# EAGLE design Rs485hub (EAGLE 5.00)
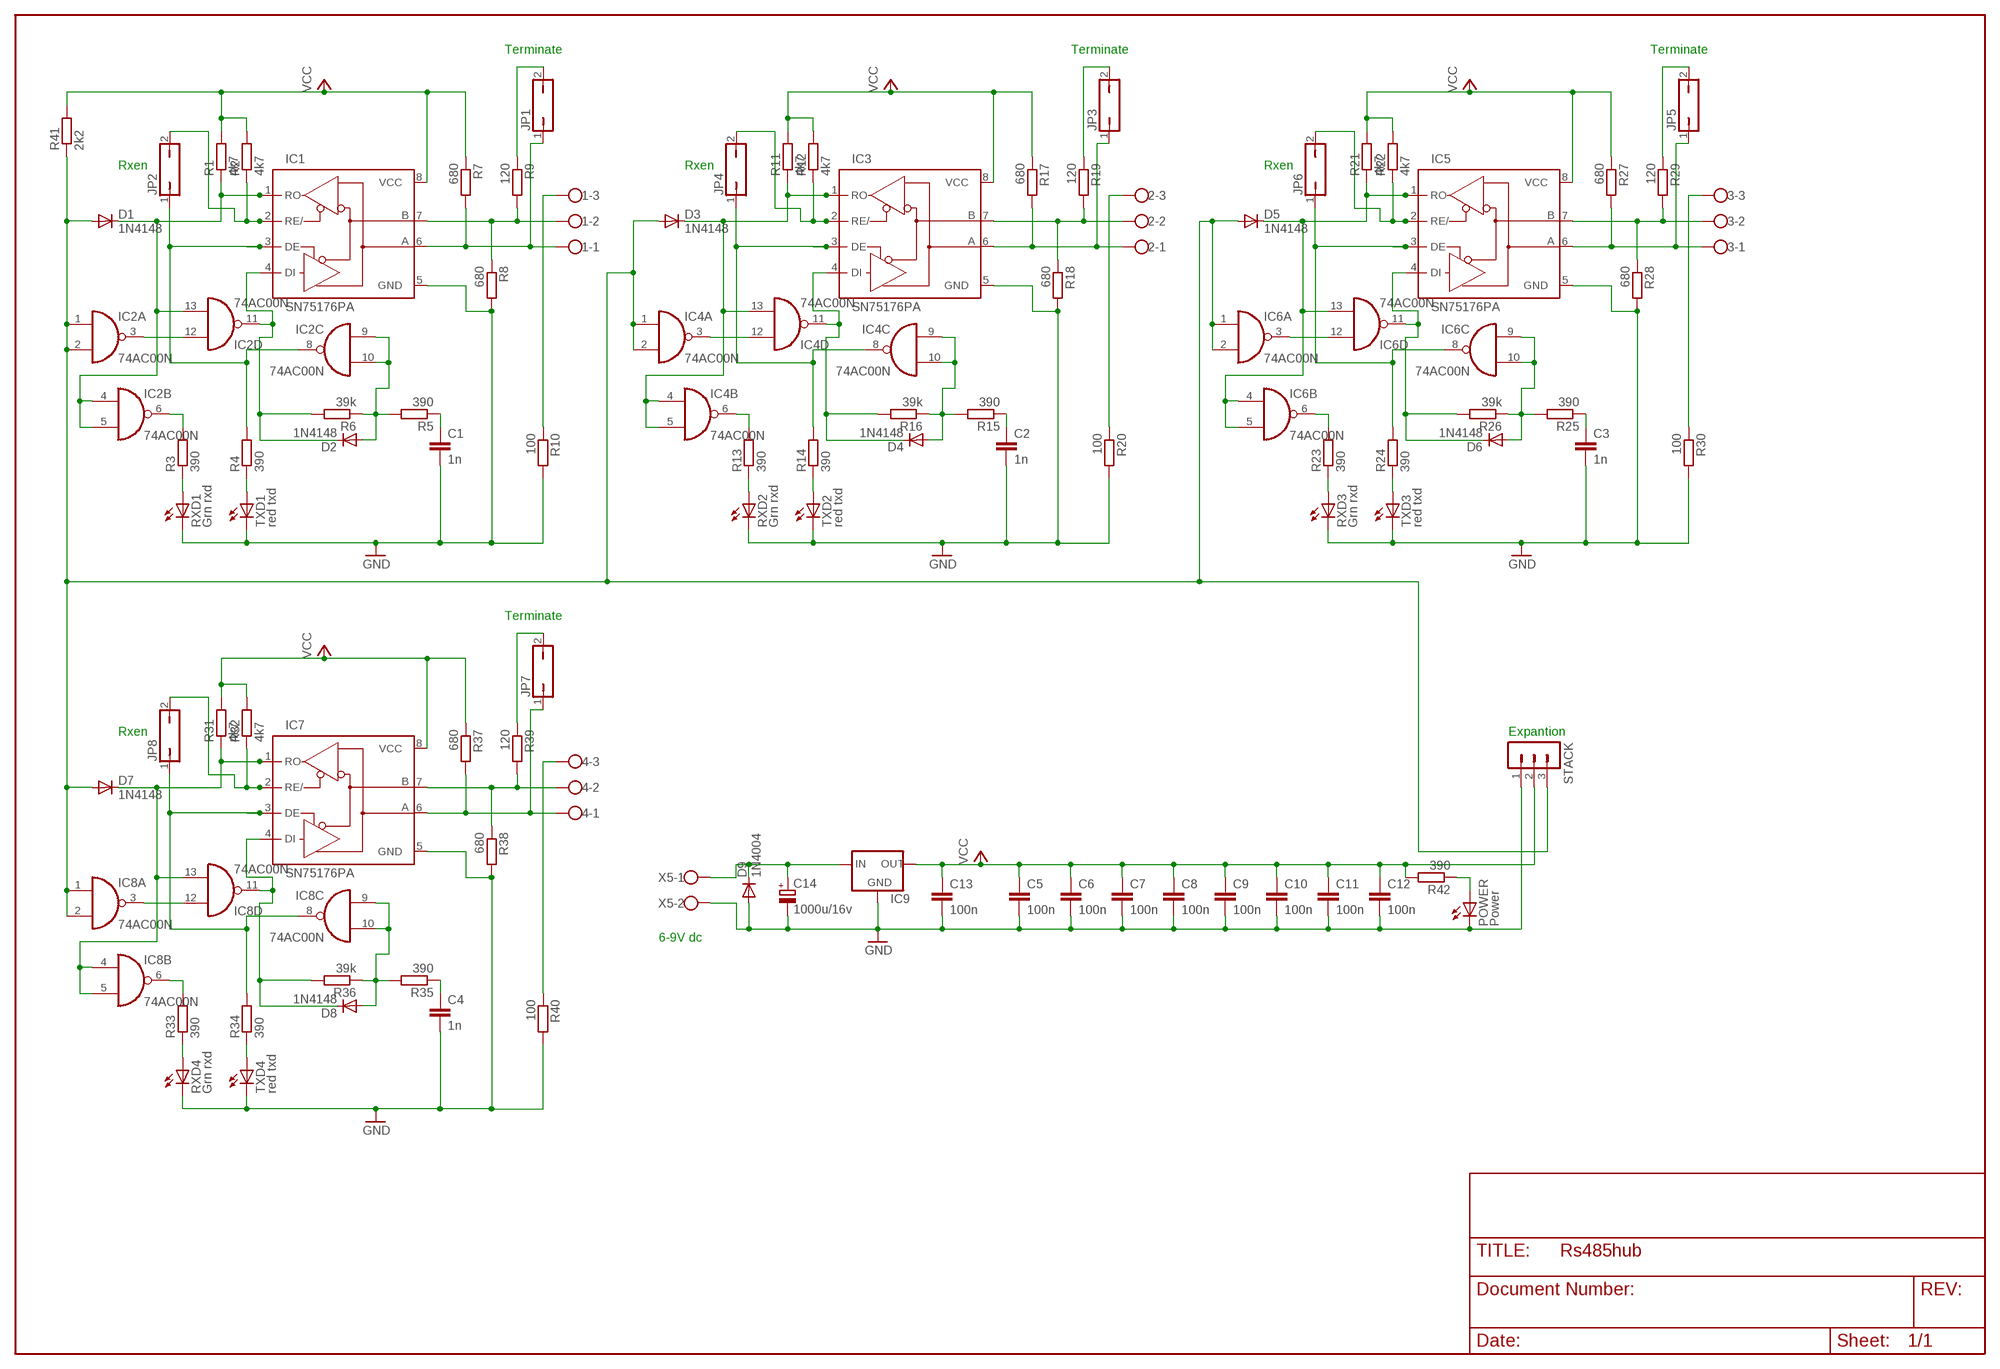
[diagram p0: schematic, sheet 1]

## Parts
1  W237-103  [W237-103]
2  W237-103  [W237-103]
3  W237-103  [W237-103]
4  W237-103  [W237-103]
C1  1n  C2,5-3  [C2.5-3]
C2  1n  C2,5-3  [C2.5-3]
C3  1n  C2,5-3  [C2.5-3]
C4  1n  C2,5-3  [C2.5-3]
C5  100n  C2,5-3  [C2.5-3]
C6  100n  C2,5-3  [C2.5-3]
C7  100n  C2,5-3  [C2.5-3]
C8  100n  C2,5-3  [C2.5-3]
C9  100n  C2,5-3  [C2.5-3]
C10  100n  C2,5-3  [C2.5-3]
C11  100n  C2,5-3  [C2.5-3]
C12  100n  C2,5-3  [C2.5-3]
C13  100n  C2,5-3  [C2.5-3]
C14  1000u/16v  CPOL-EUE5-13  [E5-13]
D1  1N4148  [DO35-10]
D2  1N4148  [DO35-10]
D3  1N4148  [DO35-10]
D4  1N4148  [DO35-10]
D5  1N4148  [DO35-10]
D6  1N4148  [DO35-10]
D7  1N4148  [DO35-10]
D8  1N4148  [DO35-10]
D9  1N4004  [DO41-10]
IC1  SN75176PA  [DIL08]
IC2  74AC00N  [DIL14]
IC3  SN75176PA  [DIL08]
IC4  74AC00N  [DIL14]
IC5  SN75176PA  [DIL08]
IC6  74AC00N  [DIL14]
IC7  SN75176PA  [DIL08]
IC8  74AC00N  [DIL14]
IC9  78XXS  [78XXS]
JP1  JP1Q  [JP1]
JP2  JP1Q  [JP1]
JP3  JP1Q  [JP1]
JP4  JP1Q  [JP1]
JP5  JP1Q  [JP1]
JP6  JP1Q  [JP1]
JP7  JP1Q  [JP1]
JP8  JP1Q  [JP1]
POWER  Power  LED3MM  [LED3MM]
R1  4k7  R-EU_0309/10  [0309/10]
R2  4k7  R-EU_0309/10  [0309/10]
R3  390  R-EU_0309/10  [0309/10]
R4  390  R-EU_0309/10  [0309/10]
R5  390  R-EU_0309/10  [0309/10]
R6  39k  R-EU_0309/10  [0309/10]
R7  680  R-EU_0309/10  [0309/10]
R8  680  R-EU_0309/10  [0309/10]
R9  120  R-EU_0309/10  [0309/10]
R10  100  R-EU_0309/10  [0309/10]
R11  4k7  R-EU_0309/10  [0309/10]
R12  4k7  R-EU_0309/10  [0309/10]
R13  390  R-EU_0309/10  [0309/10]
R14  390  R-EU_0309/10  [0309/10]
R15  390  R-EU_0309/10  [0309/10]
R16  39k  R-EU_0309/10  [0309/10]
R17  680  R-EU_0309/10  [0309/10]
R18  680  R-EU_0309/10  [0309/10]
R19  120  R-EU_0309/10  [0309/10]
R20  100  R-EU_0309/10  [0309/10]
R21  4k7  R-EU_0309/10  [0309/10]
R22  4k7  R-EU_0309/10  [0309/10]
R23  390  R-EU_0309/10  [0309/10]
R24  390  R-EU_0309/10  [0309/10]
R25  390  R-EU_0309/10  [0309/10]
R26  39k  R-EU_0309/10  [0309/10]
R27  680  R-EU_0309/10  [0309/10]
R28  680  R-EU_0309/10  [0309/10]
R29  120  R-EU_0309/10  [0309/10]
R30  100  R-EU_0309/10  [0309/10]
R31  4k7  R-EU_0309/10  [0309/10]
R32  4k7  R-EU_0309/10  [0309/10]
R33  390  R-EU_0309/10  [0309/10]
R34  390  R-EU_0309/10  [0309/10]
R35  390  R-EU_0309/10  [0309/10]
R36  39k  R-EU_0309/10  [0309/10]
R37  680  R-EU_0309/10  [0309/10]
R38  680  R-EU_0309/10  [0309/10]
R39  120  R-EU_0309/10  [0309/10]
R40  100  R-EU_0309/10  [0309/10]
R41  2k2  R-EU_0309/10  [0309/10]
R42  390  R-EU_0309/10  [0309/10]
RXD1  Grn rxd  LED3MM  [LED3MM]
RXD2  Grn rxd  LED3MM  [LED3MM]
RXD3  Grn rxd  LED3MM  [LED3MM]
RXD4  Grn rxd  LED3MM  [LED3MM]
STACK  MA03-1  [MA03-1]
TXD1  red txd  LED3MM  [LED3MM]
TXD2  red txd  LED3MM  [LED3MM]
TXD3  red txd  LED3MM  [LED3MM]
TXD4  red txd  LED3MM  [LED3MM]
X5  W237-102  [W237-102]

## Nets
DATABUS: D1.A D3.A D5.A D7.A IC2.1(A:I0) IC2.2(A:I1) IC4.1(A:I0) IC4.2(A:I1) IC6.1(A:I0) IC6.2(A:I1) IC8.1(A:I0) IC8.2(A:I1) R41.1 STACK.3
GND [Gnd]: C1.2 C2.2 C3.2 C4.2 C5.2 C6.2 C7.2 C8.2 C9.2 C10.2 C11.2 C12.2 C13.2 C14.- D9.A IC1.5(GND) IC3.5(GND) IC5.5(GND) IC7.5(GND) IC9.GND POWER.K(C) R8.2 R10.2 R18.2 R20.2 R28.2 R30.2 R38.2 R40.2 RXD1.K(C) RXD2.K(C) RXD3.K(C) RXD4.K(C) STACK.1 TXD1.K(C) TXD2.K(C) TXD3.K(C) TXD4.K(C) X5.2
N$1: R4.1 TXD1.A
N$2: R3.1 RXD1.A
N$3: 1.3 R10.1
N$4: 1.2 IC1.7(B) R8.1 R9.2
N$5: JP1.2 R9.1
N$6: R14.1 TXD2.A
N$7 [Vcc]: C14.+ D9.C IC9.IN X5.1
N$8: D1.C IC1.1(RO) IC2.4(B:I0) IC2.5(B:I1) IC2.13(D:I1) R1.1
N$9: IC2.3(A:O) IC2.12(D:I0)
N$10: 1.1 IC1.6(A) JP1.1 R7.2
N$11: IC2.6(B:O) R3.2
N$12: IC1.3(DE) IC2.8(C:O) JP2.1 R4.2
N$13: IC1.2(RE/) JP2.2 R2.1
N$14: D2.A IC2.9(C:I0) IC2.10(C:I1) R5.2 R6.1
N$15: D2.C IC1.4(DI) IC2.11(D:O) R6.2
N$16: C1.1 R5.1
N$17: R13.1 RXD2.A
N$18: 2.2 IC3.7(B) R18.1 R19.2
N$19: JP3.2 R19.1
N$20: 2.1 IC3.6(A) JP3.1 R17.2
N$22: D3.C IC3.1(RO) IC4.4(B:I0) IC4.5(B:I1) IC4.13(D:I1) R11.1
N$23: IC4.3(A:O) IC4.12(D:I0)
N$24: IC4.6(B:O) R13.2
N$25: IC3.3(DE) IC4.8(C:O) JP4.1 R14.2
N$26: D4.A IC4.9(C:I0) IC4.10(C:I1) R15.2 R16.1
N$27: D4.C IC3.4(DI) IC4.11(D:O) R16.2
N$28: C2.1 R15.1
N$29: IC3.2(RE/) JP4.2 R12.1
N$30: 2.3 R20.1
N$31: R24.1 TXD3.A
N$32: R23.1 RXD3.A
N$33: 3.2 IC5.7(B) R28.1 R29.2
N$34: JP5.2 R29.1
N$35: 3.1 IC5.6(A) JP5.1 R27.2
N$36: POWER.A R42.1
N$37: D5.C IC5.1(RO) IC6.4(B:I0) IC6.5(B:I1) IC6.13(D:I1) R21.1
N$38: IC6.3(A:O) IC6.12(D:I0)
N$39: IC6.6(B:O) R23.2
N$40: IC5.3(DE) IC6.8(C:O) JP6.1 R24.2
N$41: D6.A IC6.9(C:I0) IC6.10(C:I1) R25.2 R26.1
N$42: D6.C IC5.4(DI) IC6.11(D:O) R26.2
N$43: C3.1 R25.1
N$44: IC5.2(RE/) JP6.2 R22.1
N$45: 3.3 R30.1
N$46: R34.1 TXD4.A
N$47: R33.1 RXD4.A
N$48: 4.2 IC7.7(B) R38.1 R39.2
N$49: JP7.2 R39.1
N$50: 4.1 IC7.6(A) JP7.1 R37.2
N$52: D7.C IC7.1(RO) IC8.4(B:I0) IC8.5(B:I1) IC8.13(D:I1) R31.1
N$53: IC8.3(A:O) IC8.12(D:I0)
N$54: IC8.6(B:O) R33.2
N$55: IC7.3(DE) IC8.8(C:O) JP8.1 R34.2
N$56: D8.A IC8.9(C:I0) IC8.10(C:I1) R35.2 R36.1
N$57: D8.C IC7.4(DI) IC8.11(D:O) R36.2
N$58: C4.1 R35.1
N$59: IC7.2(RE/) JP8.2 R32.1
N$60: 4.3 R40.1
VCC [Vcc]: C5.1 C6.1 C7.1 C8.1 C9.1 C10.1 C11.1 C12.1 C13.1 IC1.8(VCC) IC3.8(VCC) IC5.8(VCC) IC7.8(VCC) IC9.OUT R1.2 R2.2 R7.1 R11.2 R12.2 R17.1 R21.2 R22.2 R27.1 R31.2 R32.2 R37.1 R41.2 R42.2 STACK.2

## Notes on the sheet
- Terminate | Terminate | Terminate
- Rxen | Rxen | Rxen
- Terminate
- Rxen | Expantion
- 6-9V dc

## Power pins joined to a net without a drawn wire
GND: IC2.7(P:GND) IC4.7(P:GND) IC6.7(P:GND) IC8.7(P:GND)
VCC: IC2.14(P:VCC) IC4.14(P:VCC) IC6.14(P:VCC) IC8.14(P:VCC)

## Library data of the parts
1-4 = con-wago-500:W237-103: WAGO SCREW CLAMP
C1-C13 = capacitor-wima:C: CAPACITOR
C14 = rcl:CPOL-EU: POLARIZED CAPACITOR, European symbol
D1-D8 = diode:1N4148: DIODE
D9 = diode:1N4004: DIODE
IC1 IC3 IC5 IC7 = Evert:SN75176: +5V, Fail-Safe, 40Mbps, Profibus RS-485/RS-422 Transceivers
IC2 IC4 IC6 IC8 = 74xx-eu:74*00: Quad 2-input NAND gate
IC9 = v-reg:78XXS: VOLTAGE REGULATOR
JP1-JP8 = jumper:JP1Q: JUMPER
POWER RXD1-RXD4 TXD1-TXD4 = led:LED: LED
R1-R42 = rcl:R-EU_: RESISTOR, European symbol
STACK = con-lstb:MA03-1: PIN HEADER
X5 = con-wago-500:W237-102: WAGO SCREW CLAMP

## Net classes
0 default: width 0.4 mm, clearance 0.254 mm
1 Vcc: width 1 mm, clearance 0.15 mm
2 Gnd: clearance 0.15 mm

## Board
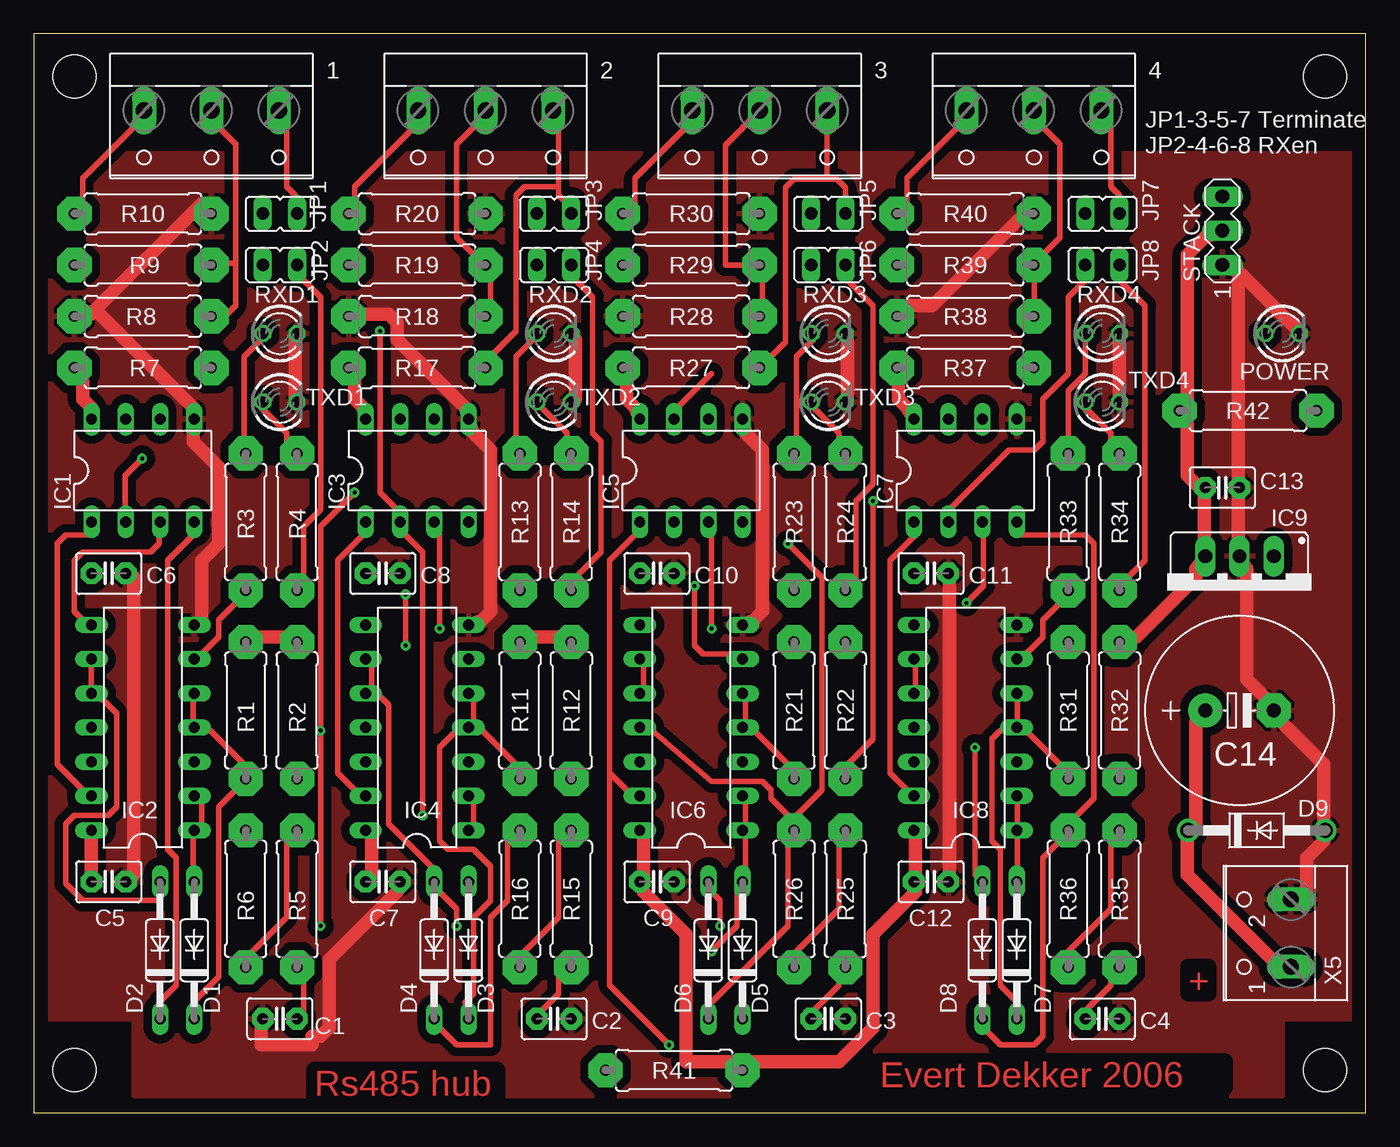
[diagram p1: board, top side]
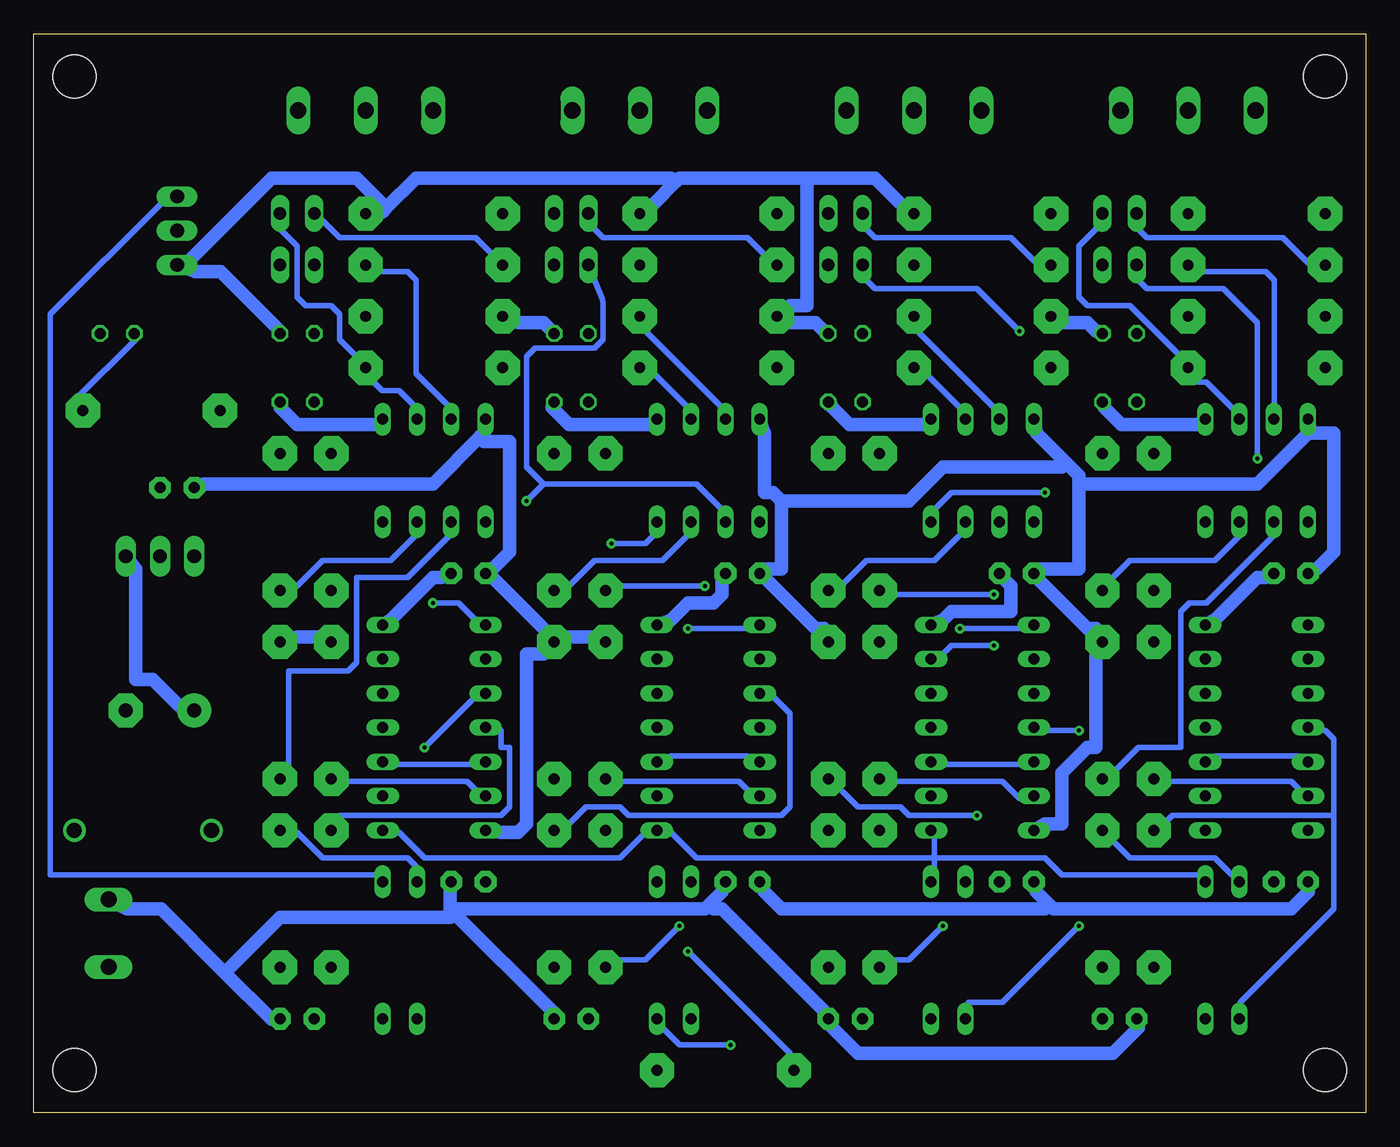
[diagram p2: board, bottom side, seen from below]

Size 98.73 x 80 mm. Coordinates in mm from the lower left corner, seen from the top.
Outline: 0,0 98.73,0 98.73,80 0,80 0,0
Copper layers (1*16): Top 0.035mm / dielectric 1.5mm / Bottom 0.035mm
Design rules "pcb-pool": minimum track width 6mil, minimum drill 12mil, track to track 6mil, track to pad 6mil, pad to pad 6mil, via to via 6mil, smd to smd 8mil, copper to edge 40mil, drill to drill 20mil, minimum pad ring 8mil, minimum via ring 8mil, stop-mask expansion 6mil, vias tented up to drill 0mil, thermal gap 10mil
Holes 3.2 mm at 3.01,76.83 3.01,3.17 95.72,76.83 95.72,3.17

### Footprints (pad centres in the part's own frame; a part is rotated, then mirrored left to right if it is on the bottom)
W237-103 = drill 1.194 long: 1 -5,-1.29; 2 0,-1.29; 3 5,-1.29
C2.5-3 = drill 0.813 pad 1.6 octagon: 1 -1.27,0; 2 1.27,0
E5-13 = drill 1.016 pad 2.54 round: + -2.54,0 | drill 1.016 pad 2.54 octagon: - 2.54,0
DO35-10 = drill 0.813 long: A 5.08,0; C -5.08,0
DO41-10 = drill 1.118 round: A 5.08,0; C -5.08,0
DIL08 = drill 0.813 long: 1 -3.81,-3.81; 2 -1.27,-3.81; 3 1.27,-3.81; 4 3.81,-3.81; 5 3.81,3.81; 6 1.27,3.81; 7 -1.27,3.81; 8 -3.81,3.81
DIL14 = drill 0.813 long: 1 -7.62,-3.81; 2 -5.08,-3.81; 3 -2.54,-3.81; 4 0,-3.81; 5 2.54,-3.81; 6 5.08,-3.81; 7 7.62,-3.81; 8 7.62,3.81; 9 5.08,3.81; 10 2.54,3.81; 11 0,3.81; 12 -2.54,3.81; 13 -5.08,3.81; 14 -7.62,3.81
78XXS = drill 1.016 long: GND 0,-2.54; IN -2.54,-2.54; OUT 2.54,-2.54
JP1 = drill 0.914 long: 1 0,-1.27; 2 0,1.27
LED3MM = drill 0.813 octagon: A -1.27,0; K 1.27,0
0309/10 = drill 0.813 pad 2.54 octagon: 1 -5.08,0; 2 5.08,0
MA03-1 = drill 1.016 long: 1 -2.54,0; 2 0,0; 3 2.54,0
W237-102 = drill 1.194 long: 1 -2.5,-1.27; 2 2.5,-1.27

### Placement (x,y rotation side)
1  13.17,73.02 180 top
2  33.49,73.02 180 top
3  53.81,73.02 180 top
4  74.13,73.02 180 top
C1  18.25,6.98 180 top
C2  38.57,6.98 0 top
C3  58.89,6.98 0 top
C4  79.21,6.98 0 top
C5  5.55,17.14 0 top
C6  5.55,40 0 top
C7  25.87,17.14 0 top
C8  25.87,40 0 top
C9  46.19,17.14 0 top
C10  46.19,40 0 top
C11  66.51,40 0 top
C12  66.51,17.14 0 top
C13  88.1,46.35 0 top
C14  89.37,29.84 0 top
D1  11.9,12.06 90 top
D2  9.36,12.06 90 top
D3  32.22,12.06 90 top
D4  29.68,12.06 90 top
D5  52.54,12.06 90 top
D6  50,12.06 90 top
D7  72.86,12.06 90 top
D8  70.32,12.06 90 top
D9  90.64,20.95 0 top
IC1  8.09,47.62 0 top
IC2  8.09,28.57 90 top
IC3  28.41,47.62 0 top
IC4  28.41,28.57 90 top
IC5  48.73,47.62 0 top
IC6  48.73,28.57 90 top
IC7  69.05,47.62 0 top
IC8  69.05,28.57 90 top
IC9  89.37,38.73 180 top
JP1  18.25,66.67 90 top
JP2  18.25,62.86 90 top
JP3  38.57,66.67 90 top
JP4  38.57,62.86 90 top
JP5  58.89,66.67 90 top
JP6  58.89,62.86 90 top
JP7  79.21,66.67 90 top
JP8  79.21,62.86 90 top
POWER  92.55,57.78 0 top
R1  15.71,29.84 90 top
R2  19.52,29.84 90 top
R3  15.71,43.81 270 top
R4  19.52,43.81 270 top
R5  19.52,15.87 90 top
R6  15.71,15.87 90 top
R7  8.09,55.24 0 top
R8  8.09,59.05 180 top
R9  8.09,62.86 0 top
R10  8.09,66.67 0 top
R11  36.03,29.84 90 top
R12  39.84,29.84 90 top
R13  36.03,43.81 270 top
R14  39.84,43.81 270 top
R15  39.84,15.87 90 top
R16  36.03,15.87 90 top
R17  28.41,55.24 0 top
R18  28.41,59.05 180 top
R19  28.41,62.86 0 top
R20  28.41,66.67 0 top
R21  56.35,29.84 90 top
R22  60.16,29.84 90 top
R23  56.35,43.81 270 top
R24  60.16,43.81 270 top
R25  60.16,15.87 90 top
R26  56.35,15.87 90 top
R27  48.73,55.24 0 top
R28  48.73,59.05 180 top
R29  48.73,62.86 0 top
R30  48.73,66.67 0 top
R31  76.67,29.84 90 top
R32  80.48,29.84 90 top
R33  76.67,43.81 270 top
R34  80.48,43.81 270 top
R35  80.48,15.87 90 top
R36  76.67,15.87 90 top
R37  69.05,55.24 0 top
R38  69.05,59.05 180 top
R39  69.05,62.86 0 top
R40  69.05,66.67 0 top
R41  47.46,3.17 0 top
R42  90,52.07 180 top
RXD1  18.25,57.78 0 top
RXD2  38.57,57.78 0 top
RXD3  58.89,57.78 0 top
RXD4  79.21,57.78 0 top
STACK  88.1,65.4 90 top
TXD1  18.25,52.7 0 top
TXD2  38.57,52.7 0 top
TXD3  58.89,52.7 0 top
TXD4  79.21,52.7 0 top
X5  91.91,13.33 90 top

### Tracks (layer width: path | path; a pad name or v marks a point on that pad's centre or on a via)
DATABUS  (via drill 0.3)
  Top 0.4: IC6.2 52.76,23.31 52.76,21.42 IC6.1 52.76,20.79 52.76,18.27 D5.A 52.13,16.38 52.13,13.86 v50.24,11.97 | D1.A 11.81,18.27 11.81,20.79 IC2.1 12.44,21.42 12.44,23.31 IC2.2 | IC4.2 32.6,23.31 32.6,21.42 IC4.1 | D7.A 72.92,18.27 72.92,20.79 IC8.1 72.92,21.42 72.92,23.31 IC8.2
  Bottom 0.4: 31.97,18.9 31.97,20.79 IC4.1 | 31.97,18.9 31.97,18.27 D3.A | 31.97,18.9 23.78,18.9 22.52,17.64 12.44,17.64 D1.A | 31.97,18.9 49.61,18.9 51.5,20.79 IC6.1 53.39,20.79 55.28,18.9 69.77,18.9 71.66,20.79 IC8.1 | v50.24,11.97 42.68,4.41 R41.1 | STACK.3 89.3,67.41 97.49,59.22 97.49,17.64 72.92,17.64 D7.A
GND
  Top 1: R40.2 72.92,66.15 66.62,59.85 64.73,59.85 R38.2 | TXD3.K 60.32,52.92 60.32,57.33 RXD3.K | IC6.7 53.39,36.54 54.02,37.17 54.02,49.14 52.76,50.4 IC5.5 | TXD2.K 40.16,52.92 40.16,57.33 RXD2.K | IC4.7 33.23,36.54 33.86,37.17 33.86,49.14 32.6,50.4 IC3.5 31.97,52.29 26.93,57.33 26.93,58.59 26.3,59.22 24.41,59.22 R18.2 | C5.2 7.4,17.64 7.4,39.69 C6.2 | TXD1.K 19.37,52.92 19.37,57.33 RXD1.K | 4.56,59.54 12.44,67.41 R10.2 | 4.56,59.54 4.25,59.22 R8.2 | 4.56,59.54 11.81,52.29 IC1.5 11.81,50.4 11.81,49.77 13.7,47.88 13.7,42.21 12.44,40.95 12.44,36.54 IC2.7 | X5.2 94.34,16.38 94.34,18.9 95.6,20.16 D9.A 95.6,21.42 95.6,25.83 92.45,28.98 C14.- 91.19,30.87 89.93,32.13 89.93,40.32 IC9.GND 89.3,42.21 89.3,45.99 C13.2 89.3,46.62 89.3,61.74 89.61,62.05 | RXD4.K TXD4.K | 89.61,62.05 89.3,62.37 STACK.1 | 89.61,62.05 93.71,57.96 POWER.K | C7.2 26.93,16.38 21.89,11.34 21.89,6.3 21.26,5.67 20.63,5.67 20.63,5.04 16.85,5.04 16.85,6.3 C1.2 | C11.2 67.88,39.69 67.88,17.64 C12.2
  Bottom 1: IC6.7 51.5,36.54 50.24,37.8 48.35,37.8 47.72,38.43 47.72,39.69 C10.2 | IC5.5 52.76,51.03 59.06,51.03 60.32,52.29 TXD3.K | RXD3.K 60.32,57.96 60.95,58.59 62.84,58.59 R38.2 | 41.42,69.3 50.87,69.3 51.19,68.98 | 41.42,69.3 36.38,69.3 34.49,67.41 R20.2 | 51.19,68.98 52.76,67.41 R30.2 | RXD2.K 40.16,57.96 40.79,58.59 42.68,58.59 R28.2 42.68,59.85 41.42,59.85 41.42,69.3 | C8.2 26.93,39.69 26.3,39.06 26.3,37.17 30.71,37.17 31.34,36.54 IC4.7 | TXD2.K 39.53,52.29 38.27,51.03 32.6,51.03 IC3.5 | IC2.7 11.18,36.54 8.03,39.69 7.4,39.69 C6.2 | IC1.5 12.44,51.03 18.11,51.03 19.37,52.29 TXD1.K | RXD1.K 20,57.96 20.63,58.59 22.52,58.59 R18.2 | 72.61,67.09 70.4,69.3 51.5,69.3 51.19,68.98 | 72.61,67.09 72.92,66.78 R40.2 | 84.58,10.4 89.3,15.12 91.82,15.12 X5.2 | 84.58,10.4 81.11,6.93 C4.2 | IC7.5 72.92,51.03 79.22,51.03 80.48,52.29 TXD4.K | RXD4.K 80.48,57.96 84.89,62.37 86.78,62.37 STACK.1 87.41,63 81.11,69.3 74.81,69.3 72.61,67.09 | C1.2 16.85,6.3 18.74,4.41 37.64,4.41 39.53,6.3 C2.2 40.16,7.56 47.72,15.12 48.35,15.12 48.66,15.44 | IC8.7 72.29,36.54 69.14,39.69 68.51,39.69 C11.2 | 67.56,14.81 67.88,15.12 67.88,16.38 C12.2 | 67.56,14.81 60.32,7.56 C3.2 | 48.66,15.44 48.98,15.12 67.25,15.12 67.56,14.81 | 48.66,15.44 47.72,16.38 C9.2 | 84.58,10.4 80.48,14.49 67.88,14.49 67.56,14.81
  pour Top (isolate 0.61): 1.1,71.11 97.62,71.11 97.62,6.98 92.55,6.98 92.55,1.27 7.46,1.27 7.46,6.98 1.1,6.98
N$1
  Top 0.4: TXD1.A 16.85,52.29 18.74,50.4 18.74,49.77 R4.1
N$2
  Top 0.4: RXD1.A 16.85,57.33 15.59,56.07 15.59,49.77 R3.1
N$3
  Top 0.4: 1.3 7.4,73.08 3.62,69.3 3.62,67.41 R10.1
N$4
  Top 0.4: 14.96,62.98 14.96,71.82 13.7,73.08 1.2 | 14.96,62.98 13.7,63 R9.2 | 14.96,62.98 14.96,59.85 14.33,59.22 R8.1
  Bottom 0.4: IC1.7 6.77,52.29 6.77,61.73 7.4,62.37 12.44,62.37 R9.2
N$5
  Bottom 0.4: JP1.2 16.85,65.52 16.22,64.89 6.14,64.89 4.25,63 R9.1
N$6
  Top 0.4: TXD2.A 37.64,52.29 39.53,50.4 39.53,49.77 R14.1
N$7
  Top 1: C14.+ 86.15,28.98 86.15,21.42 D9.C 85.52,20.16 85.52,17.64 91.82,11.34 X5.1
  Bottom 1: IC9.IN 91.19,40.32 91.19,32.13 89.93,32.13 88.04,30.24 C14.+
N$8
  Top 0.4: IC2.5 11.81,30.87 11.81,28.98 IC2.4 13.07,28.35 15.59,25.83 R1.1 14.96,23.94 13.7,22.68 13.7,10.08 11.81,8.19 D1.C | IC1.1 4.25,42.84 2.37,42.84 1.73,42.21 1.73,25.83 3.62,23.94 IC2.13
  Bottom 0.4: IC2.13 4.88,23.94 5.51,24.57 14.96,24.57 R1.1
N$9
  Bottom 0.4: IC2.12 4.88,26.46 11.18,26.46 IC2.3
N$10
  Top 0.4: JP1.1 19.37,68.04 18.74,68.67 18.74,73.08 1.1
  Bottom 0.4: JP1.1 20,65.52 21.26,64.26 21.26,60.48 20.62,59.85 17.48,59.85 13.7,56.07 R7.2 12.44,54.18 11.81,54.18 9.92,52.29 IC1.6
N$11
  Top 0.4: IC2.6 12.44,34.02 13.7,35.28 13.7,36.54 14.96,37.8 R3.2
N$12
  Top 0.4: IC2.8 3.62,36.54 2.99,37.17 2.99,40.95 3.62,41.58 8.66,41.58 9.29,42.22 9.29,42.84 IC1.3 | JP2.1 20,61.74 21.26,60.48 21.26,44.73 20,43.47 20,39.69 R4.2
  Bottom 0.4: IC1.3 9.29,42.84 11.18,40.95 17.48,40.95 18.74,39.69 R4.2
N$13  (via drill 0.3)
  Top 0.4: v8.03,48.51 6.77,47.25 6.77,44.73 IC1.2
  Bottom 0.4: IC1.2 6.77,42.84 11.81,37.8 13.07,37.8 13.7,37.17 13.7,27.09 16.85,27.09 18.74,25.2 R2.1 | v8.03,48.51 8.03,58.59 10.55,61.11 16.22,61.11 16.85,61.74 JP2.2
N$14
  Top 0.4: IC2.9 4.25,33.39 4.25,31.5 IC2.10 4.88,30.87 6.14,29.61 6.14,22.68 5.51,22.05 3,22.05 2.36,21.41 2.36,17.01 3.62,15.75 9.29,15.75 9.29,16.38 D2.A | R6.1 16.22,11.97 18.74,14.49 18.74,20.16 R5.2
  Bottom 0.4: D2.A 9.92,17.64 11.18,18.9 17.48,18.9 18.74,20.16 R5.2
N$15
  Top 0.4: IC1.4 11.81,42.84 9.92,40.95 9.92,19.53 10.55,18.9 10.55,9.45 9.29,8.19 D2.C
  Bottom 0.4: 2.36,22.05 2.36,15.12 9.29,8.19 D2.C | 2.36,22.05 2.36,27.71 3,28.35 3.62,28.35 IC2.11 | 2.36,22.05 14.33,22.05 14.96,21.42 R6.2
N$16
  Top 0.4: C1.1 20,7.56 20,10.08 R5.1
N$17
  Top 0.4: RXD2.A 37.01,57.33 35.75,56.07 35.75,49.77 R13.1
N$18
  Top 0.4: 2.2 32.6,73.08 31.34,71.82 31.34,64.89 32.6,63.63 R19.2 33.86,61.74 33.86,59.85 R18.1
  Bottom 0.4: R18.1 33.23,57.96 27.56,52.29 IC3.7
N$19
  Bottom 0.4: JP3.2 37.01,65.52 36.38,64.89 26.3,64.89 24.41,63 R19.1
N$20
  Top 0.4: 38.9,68.67 38.9,73.08 2.1 | 38.9,68.67 38.9,68.04 39.53,67.41 JP3.1 | 38.9,68.67 36.38,68.67 35.75,68.03 35.75,57.96 33.86,56.07 R17.2
  Bottom 0.4: IC3.6 30.08,52.29 32.6,54.81 R17.2
N$22
  Top 0.4: D3.C 31.97,8.19 32.6,8.82 32.6,14.49 33.86,15.75 33.86,18.27 32.6,19.53 30.71,19.53 30.08,20.16 30.08,27.09 31.34,28.35 IC4.4 | IC4.5 32.6,30.87 32.6,28.98 IC4.4 | IC3.1 24.41,42.84 22.52,40.95 22.52,25.2 23.78,23.94 IC4.13 | IC4.4 33.23,28.35 35.75,25.83 R11.1
  Bottom 0.4: IC4.13 25.67,23.31 26.93,24.57 35.12,24.57 R11.1
N$23
  Bottom 0.4: IC4.12 25.67,25.83 31.34,25.83 IC4.3
N$24  (via drill 0.3)
  Top 0.4: v27.56,34.65 v27.56,38.43
  Bottom 0.4: v27.56,34.65 30.71,34.65 31.34,34.02 IC4.6 | v27.56,38.43 35.12,38.43 R13.2
N$25  (via drill 0.3)
  Top 0.4: v30.08,35.91 30.08,42.84 IC3.3 | JP4.1 40.16,61.74 41.42,60.48 41.42,50.4 42.05,49.77 42.05,41.58 40.16,39.69 R14.2
  Bottom 0.4: v30.08,35.91 25.67,35.91 IC4.8 | IC3.3 30.08,42.84 31.97,40.95 37.01,40.95 38.9,39.06 R14.2
N$26  (via drill 0.3)
  Top 0.4: IC4.9 25.04,33.39 25.04,31.5 IC4.10 25.67,30.87 26.3,30.24 26.3,21.42 29.45,18.27 D4.A 30.08,16.38 31.34,15.12 v31.34,13.86 | R16.1 36.38,11.97 38.9,14.49 38.9,20.16 R15.2
  Bottom 0.4: v31.34,13.86 33.86,11.34 35.12,11.34 R16.1
N$27  (via drill 0.3)
  Top 0.4: D4.C 30.08,6.3 31.34,5.04 33.86,5.04 33.86,14.49 35.12,15.75 35.12,20.16 R16.2 | v21.26,13.86 v21.26,28.35 21.26,43.47 v23.78,45.99
  Bottom 0.4: v21.26,28.35 23.78,28.35 IC4.11 | v21.26,13.86 26.93,8.19 29.45,8.19 D4.C | v23.78,45.99 30.71,45.99 31.97,44.73 IC3.4
N$28
  Top 0.4: C2.1 37.64,7.56 38.9,8.82 38.9,10.08 R15.1
N$29  (via drill 0.3)
  Top 0.4: v25.67,57.96 25.67,45.99 26.93,44.73 IC3.2 27.56,42.84 28.82,41.58 v28.82,22.05
  Bottom 0.4: v25.67,57.96 28.82,61.11 36.38,61.11 37.01,61.74 JP4.2 | v28.82,22.05 33.86,22.05 34.49,22.68 37.64,22.68 38.9,23.94 R12.1
N$30
  Top 0.4: 2.3 28.19,73.08 23.78,68.67 23.78,67.41 R20.1
N$31
  Top 0.4: TXD3.A 57.8,52.29 59.69,50.4 59.69,49.77 R24.1
N$32
  Top 0.4: RXD3.A 57.8,57.33 56.54,56.07 56.54,49.77 R23.1
N$33
  Top 0.4: 50.24,54.81 47.72,52.29 IC5.7 | R28.1 54.02,59.85 54.02,61.74 R29.2
  Top 0.406: 3.2 53.81,74.29 51.27,71.75 51.27,62.86 R29.2
  Bottom 0.4: IC5.7 47.72,52.29 53.39,57.96 R28.1
N$34
  Bottom 0.4: JP5.2 57.17,65.52 56.54,64.89 45.83,64.89 44.57,63.63 R29.1
N$35
  Top 0.4: R27.2 52.76,55.44 | 58.89,75.6 59.06,75.6 3.1
  Top 0.406: JP5.1 60.16,68.57 59.52,69.21 58.89,69.21 | 58.89,75.6 58.43,75.6 | R27.2 55.71,57.15 55.71,68.57 56.35,69.21 58.89,69.21 | 3.1 58.81,69.29 58.89,69.21
  Bottom 0.4: IC5.6 50.24,52.29 52.76,54.81 R27.2
N$36
  Bottom 0.4: POWER.A 91.19,57.33 95.6,52.92 R42.1
N$37  (via drill 0.3)
  Top 0.4: IC6.5 52.76,30.87 52.76,28.98 IC6.4 53.39,28.35 55.91,25.83 R21.1 | 42.68,25.2 42.68,40.95 44.57,42.84 IC5.1 | 42.68,25.2 43.94,23.94 IC6.13 | v47.09,5.04 42.68,9.45 42.68,25.2
  Bottom 0.4: IC6.13 45.83,23.94 46.46,24.57 55.28,24.57 R21.1 | v47.09,5.04 50.87,5.04 52.13,6.3 D5.C
N$38
  Bottom 0.4: IC6.12 45.83,26.46 51.5,26.46 IC6.3
N$39  (via drill 0.3)
  Top 0.4: v48.98,39.06 48.98,34.66 49.62,34.02 51.5,34.02 IC6.6
  Bottom 0.4: v48.98,39.06 55.28,39.06 R23.2
N$40  (via drill 0.3)
  Top 0.4: v50.24,35.91 50.24,42.84 IC5.3 | JP6.1 60.32,61.74 62.21,59.85 62.21,46.62 60.95,45.36 60.95,39.69 R24.2
  Bottom 0.4: v50.24,35.91 45.83,35.91 IC6.8 | IC5.3 50.24,42.84 52.13,40.95 57.17,40.95 59.06,39.06 R24.2
N$41  (via drill 0.3)
  Top 0.4: v50.87,13.86 50.87,15.75 50.24,16.38 D6.A | IC6.10 45.2,31.5 45.2,33.39 IC6.9 | R26.1 56.54,11.97 59.69,15.12 59.69,20.16 R25.2
  Bottom 0.4: v50.87,13.86 53.39,11.34 55.28,11.34 R26.1 | IC6.10 43.94,30.87 42.68,29.61 42.68,22.68 43.31,22.05 54.65,22.05 55.28,22.68 57.8,22.68 59.06,21.42 R25.2
N$42  (via drill 0.3)
  Top 0.4: D6.C 50.24,8.19 55.91,13.86 55.91,20.16 R26.2 | IC6.11 45.83,28.35 50.24,24.57 50.87,24.57 54.02,24.57 54.65,23.94 54.65,23.31 55.91,22.05 R26.2 | v55.91,42.21 58.43,39.69 58.43,23.94 56.54,22.05 R26.2
  Bottom 0.4: v55.91,42.21 53.39,42.21 52.76,42.84 IC5.4
N$43
  Top 0.4: C3.1 57.8,7.56 59.69,9.45 59.69,10.08 R25.1
N$44  (via drill 0.3)
  Top 0.4: v62.21,45.36 62.21,27.72 60.32,25.83 R22.1
  Bottom 0.4: 60.95,46.62 49.61,46.62 47.72,44.73 IC5.2 | 60.95,46.62 62.21,47.88 62.21,56.07 61.57,56.7 57.17,56.7 56.54,57.34 56.54,60.05 56.59,60.29 JP6.2 | v62.21,45.36 60.95,46.62
N$45
  Top 0.4: 3.3 48.35,73.08 44.57,69.3 44.57,67.41 R30.1
N$46
  Top 0.4: TXD4.A 77.96,52.29 79.85,50.4 79.85,49.77 R34.1
N$47
  Top 0.4: RXD4.A 77.96,57.33 77.96,54.81 76.7,53.55 76.7,49.77 R33.1
N$48
  Top 0.4: 4.2 74.81,73.08 76.07,71.82 76.07,64.89 74.81,63.63 R39.2 74.18,61.74 74.18,59.85 R38.1
  Bottom 0.4: IC7.7 67.88,52.29 70.4,54.81 70.4,61.73 71.03,62.37 72.92,62.37 R39.2
N$49
  Bottom 0.4: JP7.2 77.33,66.15 76.07,64.89 65.99,64.89 64.73,63.63 R39.1
N$50
  Top 0.4: JP7.1 80.48,68.04 79.85,68.67 79.85,73.08 4.1
  Bottom 0.4: JP7.1 80.48,65.52 79.22,64.26 79.22,60.48 78.58,59.85 76.7,59.85 76.07,59.22 76.07,57.33 74.81,56.07 R37.2 73.55,54.18 72.92,53.55 71.66,53.55 70.4,52.29 IC7.6
N$52
  Top 0.4: D7.C 72.92,8.19 71.66,9.45 71.66,19.53 71.03,20.16 71.03,27.72 71.66,28.35 IC8.4 | IC8.5 72.92,30.87 72.92,28.98 IC8.4 | IC7.1 65.36,42.84 63.47,40.95 63.47,25.2 64.73,23.94 IC8.13 | IC8.4 73.55,28.35 76.07,25.83 R31.1
  Bottom 0.4: IC8.13 65.99,23.94 66.62,24.57 75.44,24.57 R31.1
N$53
  Bottom 0.4: IC8.12 65.99,25.83 71.66,25.83 IC8.3
N$54
  Top 0.4: IC8.6 73.55,34.02 74.81,35.28 74.81,36.54 76.07,37.8 R33.2
N$55  (via drill 0.3)
  Top 0.4: v69.14,37.8 70.4,39.06 70.4,42.84 IC7.3 | JP8.1 80.48,61.74 82.37,59.85 82.37,40.95 81.11,39.69 R34.2
  Bottom 0.4: v69.14,37.8 67.25,37.8 65.99,36.54 IC8.8 | IC7.3 70.4,42.84 72.29,40.95 77.33,40.95 79.22,39.06 R34.2
N$56  (via drill 0.3)
  Top 0.4: IC8.10 65.36,31.5 65.36,33.39 IC8.9 | v69.77,27.09 69.77,17.64 D8.A | R36.1 76.7,11.97 79.85,15.12 79.85,20.16 R35.2
  Bottom 0.4: D8.A 70.4,18.27 71.03,18.9 77.33,18.9 79.22,20.79 R35.2 | v69.77,27.09 65.99,30.87 IC8.10
N$57
  Top 0.4: IC7.4 72.92,42.84 77.95,42.84 78.59,42.21 78.59,23.31 77.33,22.05 R36.2 76.07,20.16 74.81,18.9 74.81,5.67 74.17,5.04 71.66,5.04 70.4,6.3 D8.C
  Bottom 0.4: IC8.11 64.1,28.35 64.1,27.09 63.47,27.09 63.47,22.68 64.11,22.05 76.07,22.05 R36.2
N$58
  Top 0.4: C4.1 77.96,7.56 79.85,9.45 79.85,10.08 R35.1
N$59
  Top 0.4: IC7.2 67.88,44.73 72.29,49.14 74.17,49.14 74.81,49.78 74.81,52.92 76.7,54.81 76.7,60.48 77.96,61.74 JP8.2
  Bottom 0.4: R32.1 79.85,25.83 79.85,32.76 75.44,32.76 74.81,33.39 74.81,39.69 71.03,39.69 67.88,42.84 IC7.2
N$60
  Top 0.4: 4.3 68.51,73.08 64.73,69.3 64.73,67.41 R40.1
VCC
  Top 1: IC8.14 65.36,20.79 65.36,17.64 C12.1 65.36,16.38 62.21,13.23 62.21,6.3 59.69,3.78 53.39,3.78 R41.2 51.5,3.78 48.35,3.78 48.35,13.23 45.2,16.38 C9.1 45.2,17.64 45.2,20.79 IC6.14 | IC7.8 64.73,52.29 64.1,52.92 64.1,54.18 R37.1 | STACK.2 86.78,64.89 85.52,63.63 85.52,52.92 R42.2 85.52,51.03 85.52,47.25 86.15,46.62 C13.1 86.78,45.99 86.78,42.21 IC9.OUT 86.15,40.32 86.15,39.69 81.74,35.28 R32.2 | IC5.8 44.57,52.29 43.94,52.92 43.94,54.18 R27.1 | R11.2 37.01,35.28 38.9,35.28 R12.2 | IC1.8 4.25,52.29 3.62,52.92 3.62,54.18 R7.1 | IC3.8 24.41,52.29 23.78,52.92 23.78,54.18 R17.1 | R1.2 16.85,35.28 18.74,35.28 R2.2 | IC2.14 4.25,20.79 4.25,17.64 C5.1 | IC4.14 25.04,20.79 25.04,17.64 C7.1
  Bottom 1: R22.2 60.95,35.91 64.73,39.69 C11.1 64.73,40.32 63.47,41.58 63.47,49.77 65.36,49.77 65.67,50.09 | IC8.14 64.1,20.79 62.84,20.79 62.21,21.42 62.21,34.02 60.95,34.02 R22.2 | R21.2 57.17,35.28 59.06,35.28 R22.2 | R31.2 77.33,35.28 79.22,35.28 R32.2 | 65.67,50.09 69.14,46.62 86.15,46.62 C13.1 | 65.67,50.09 65.36,50.4 IC7.8 | R12.2 40.16,35.91 40.79,35.91 44.57,39.69 C10.1 44.57,40.32 43.31,40.32 43.31,45.36 | 43.31,45.36 43.94,45.99 44.57,45.99 44.57,50.4 IC5.8 | 4.25,50.4 2.36,50.4 2.36,41.58 3.62,40.32 C6.1 | 22.2,48.2 21.26,47.25 21.26,46.62 | 22.2,48.2 24.41,50.4 IC3.8 | 21.26,46.62 21.26,40.32 24.41,40.32 C8.1 24.41,39.69 20.63,35.91 20,35.91 R2.2 20,34.02 20,27.09 20.63,27.09 22.52,25.2 22.52,21.42 23.78,21.42 IC4.14 | 4.25,50.4 8.03,46.62 21.26,46.62 | 4.25,50.4 IC1.8 | 43.31,45.36 33.86,45.36 31.34,47.88 22.52,47.88 22.2,48.2 | 23.46,15.44 24.41,16.38 C7.1 | 23.46,15.44 23.15,15.12 5.51,15.12 4.25,16.38 C5.1 | C9.1 44.57,16.38 43.31,15.12 23.78,15.12 23.46,15.44

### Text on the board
Top: + | Rs485 hub | Evert Dekker 2006
tNames: JP1-3-5-7 Terminate | JP2-4-6-8 RXen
